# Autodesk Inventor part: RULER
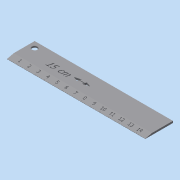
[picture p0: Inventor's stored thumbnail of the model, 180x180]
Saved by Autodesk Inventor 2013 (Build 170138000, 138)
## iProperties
Created: 2014-03
Part Number: RULER
Material: Generic
Document SubType Name: Modeling
Designer: max
Density: 1 g/cm^3
Author: max
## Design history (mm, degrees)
sketch "Schizzo1"
  geometry: L1 (0, 0)-(150, 0); L2 (150, 0)-(150, 30); L3 (150, 30)-(0, 30); L4 (0, 30)-(0, 0); L5 (10, 7.5)-(10, 0); L6 (20, 7.5)-(20, 0); L7 (30, 7.5)-(30, 0); L8 (40, 7.5)-(40, 0); L9 (50, 7.5)-(50, 0); L10 (60, 7.5)-(60, 0); L11 (70, 7.5)-(70, 0); L12 (80, 7.5)-(80, 0); L13 (90, 7.5)-(90, 0); L14 (100, 7.5)-(100, 0); L15 (110, 7.5)-(110, 0); L16 (120, 7.5)-(120, 0); L17 (130, 7.5)-(130, 0); L18 (150, 30)-(150, 0); L19 (140, 7.5)-(140, 0); L20 (0, 7.5)-(150, 7.5); C1 r 2.82 at (6.501, 23.543)
  constraints: 40 end point, 3 perpendicular, 2 point on line, 1 centre point, 1 horizontal, 1 parallel
extrude "Estrusione1" new body sketch "Schizzo1" distance "d0" = 2; taper "d1" = 0 deg
chamfer "Smusso1" distance "d2" = 7.5; stored, may be unused: second distance "d3" = 1.75, angle "d4" = 45 deg
sketch "Schizzo2"
  geometry: L1 (150, -7.701)-(150, 0) reference; L2 (150, 0)-(0, 0) reference; L3 (0, 0)-(0, -7.701) reference; L4 (0, -7.701)-(150, -7.701) reference; L5 (10, -0.454)-(10, -7.758) reference; L6 (20, -0.454)-(20, -7.758) reference; L7 (30, -0.454)-(30, -7.758) reference; L8 (40, -0.454)-(40, -7.758) reference; L9 (50, -0.454)-(50, -7.758) reference; L10 (60, -0.454)-(60, -7.758) reference; L11 (70, -0.454)-(70, -7.758) reference; L12 (80, -0.454)-(80, -7.758) reference; L13 (90, -0.454)-(90, -7.758) reference; L14 (100, -0.454)-(100, -7.758) reference; L15 (110, -0.454)-(110, -7.758) reference; L16 (120, -0.454)-(120, -7.758) reference; L17 (130, -0.454)-(130, -7.758) reference; L18 (140, -0.454)-(140, -7.758) reference; 1 further point
node "Piano di lavoro1"
sketch "Schizzo3"
  geometry: C1 r 0.25 at (10, -0.235); C2 r 0.25 at (20, -0.235); C3 r 0.25 at (30, -0.235); C4 r 0.25 at (40, -0.235); C5 r 0.25 at (50, -0.235); C6 r 0.25 at (60, -0.235); C7 r 0.25 at (70, -0.235); C8 r 0.25 at (80, -0.235); C9 r 0.25 at (90, -0.235); C10 r 0.25 at (100, -0.235); C11 r 0.25 at (110, -0.235); C12 r 0.25 at (120, -0.235); C13 r 0.25 at (130, -0.235); C14 r 0.25 at (140, -0.235); 1 further point
  constraints: 14 centre point
extrude "Estrusione2" cut sketch "Schizzo3" distance "d6" = 7.75; taper "d7" = 0 deg
extrude "Estrusione3" cut sketch "Schizzo3" distance "d8" = 7.75; taper "d9" = 0 deg
extrude "Estrusione4" cut sketch "Schizzo3" distance "d10" = 7.75; taper "d11" = 0 deg
fillet "Raccordo1" dims "d12" = 0.5
sketch "Schizzo6"
  geometry: L1 (27.232, 19.656)-(72.737, 19.656); L2 (72.737, 19.656)-(72.737, 13.408); L3 (72.737, 13.408)-(27.232, 13.408); L4 (27.232, 13.408)-(27.232, 19.656); 1 further point
  constraints: 2 other
extrude "Estrusione6" cut sketch "Schizzo6" distance "d15" = 2; taper "d16" = 0 deg
sketch "Schizzo7"
  geometry: L1 (8.545, -1.54)-(11.172, -1.54); L2 (11.172, -1.54)-(11.172, -5.051); L3 (11.172, -5.051)-(8.545, -5.051); L4 (8.545, -5.051)-(8.545, -1.54); L5 (18.811, -1.498)-(21.437, -1.498); L6 (21.437, -1.498)-(21.437, -5.071); L7 (21.437, -5.071)-(18.811, -5.071); L8 (18.811, -5.071)-(18.811, -1.498); L9 (28.833, -1.394)-(31.459, -1.394); L10 (31.459, -1.394)-(31.459, -5.041); L11 (31.459, -5.041)-(28.833, -5.041); L12 (28.833, -5.041)-(28.833, -1.394); L13 (38.69, -1.528)-(41.316, -1.528); L14 (41.316, -1.528)-(41.316, -5.028); L15 (41.316, -5.028)-(38.69, -5.028); L16 (38.69, -5.028)-(38.69, -1.528); L17 (48.91, -1.449)-(51.537, -1.449); L18 (51.537, -1.449)-(51.537, -5.023); L19 (51.537, -5.023)-(48.91, -5.023); L20 (48.91, -5.023)-(48.91, -1.449); L21 (58.794, -1.42)-(61.421, -1.42); L22 (61.421, -1.42)-(61.421, -5.059); L23 (61.421, -5.059)-(58.794, -5.059); L24 (58.794, -5.059)-(58.794, -1.42); L25 (68.825, -1.567)-(71.452, -1.567); L26 (71.452, -1.567)-(71.452, -5.067); L27 (71.452, -5.067)-(68.825, -5.067); L28 (68.825, -5.067)-(68.825, -1.567); L29 (78.802, -1.4)-(81.429, -1.4); L30 (81.429, -1.4)-(81.429, -5.059); L31 (81.429, -5.059)-(78.802, -5.059); L32 (78.802, -5.059)-(78.802, -1.4); L33 (88.858, -1.364)-(91.484, -1.364); L34 (91.484, -1.364)-(91.484, -5.003); L35 (91.484, -5.003)-(88.858, -5.003); L36 (88.858, -5.003)-(88.858, -1.364); L37 (97.545, -1.402)-(102.798, -1.402); L38 (102.798, -1.402)-(102.798, -5.046); L39 (102.798, -5.046)-(97.545, -5.046); L40 (97.545, -5.046)-(97.545, -1.402); L41 (107.273, -1.544)-(112.526, -1.544); L42 (112.526, -1.544)-(112.526, -5.055); L43 (112.526, -5.055)-(107.273, -5.055); L44 (107.273, -5.055)-(107.273, -1.544); L45 (117.31, -1.503)-(122.562, -1.503); L46 (122.562, -1.503)-(122.562, -5.077); L47 (122.562, -5.077)-(117.31, -5.077); L48 (117.31, -5.077)-(117.31, -1.503); L49 (127.424, -1.419)-(132.677, -1.419); L50 (132.677, -1.419)-(132.677, -5.066); L51 (132.677, -5.066)-(127.424, -5.066); L52 (127.424, -5.066)-(127.424, -1.419); L53 (137.103, -1.553)-(142.356, -1.553); L54 (142.356, -1.553)-(142.356, -5.064); L55 (142.356, -5.064)-(137.103, -5.064); L56 (137.103, -5.064)-(137.103, -1.553); 1 further point
  constraints: 28 other
extrude "Estrusione7" cut sketch "Schizzo7" distance "d17" = 0.75; taper "d18" = 0 deg
node "Solido1"
other parameters: "d5" = 110 deg
